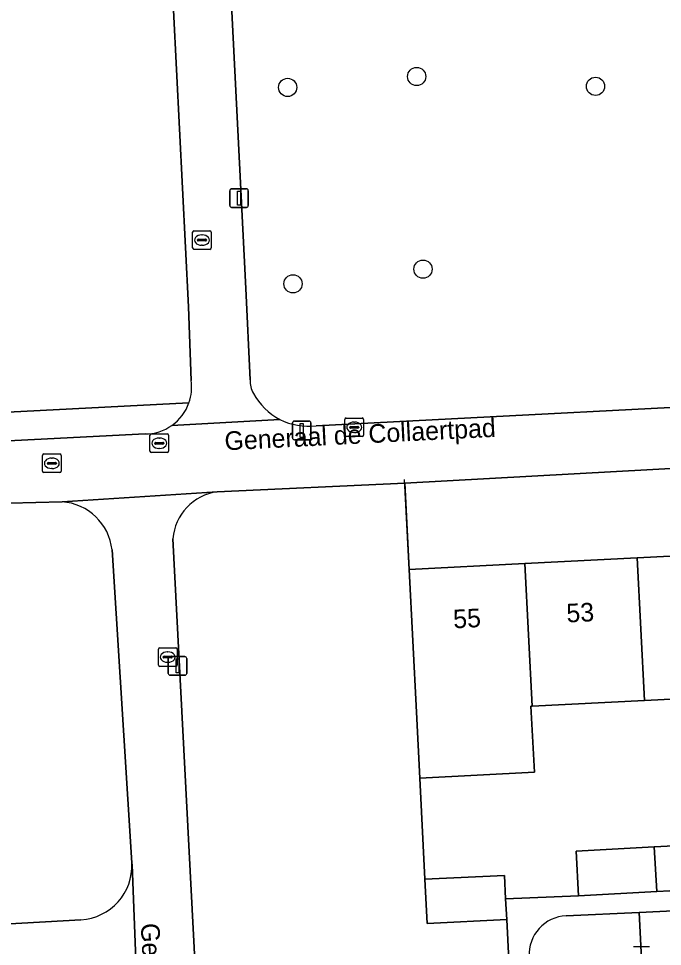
# Model space of a CAD drawing. Extents: x 161084 to 161928, y 385354 to 386522.
# Drawn here: x 161354.6 to 161389.16, y 385539.9 to 385589.73 of the extents above; entities that cross this region are included whole.
import ezdxf

# ---------------------------------------------------------------- set-up
doc = ezdxf.new("R2010")
doc.units = 0
for name, color, linetype in [('IMGEO_Boom', 7, 'Continuous'), ('IMGEO_Brandkraan', 7, 'Continuous'), ('IMGEO_Erf', 7, 'Continuous'), ('IMGEO_Groenvoorziening', 7, 'Continuous'), ('IMGEO_Hek', 7, 'Continuous'), ('IMGEO_Kolk', 7, 'Continuous'), ('IMGEO_Lichtmast', 7, 'Continuous'), ('IMGEO_Openbare_ruimte_label', 7, 'Continuous'), ('IMGEO_Pand', 7, 'Continuous'), ('IMGEO_Pand_nummerreeks', 7, 'Continuous'), ('IMGEO_Parkeervlak_open', 7, 'Continuous'), ('IMGEO_Rijbaan_lokaal_open', 7, 'Continuous'), ('IMGEO_Rioolput', 7, 'Continuous'), ('IMGEO_Voetpad_open', 7, 'Continuous')]:
    doc.layers.add(name, color=color, linetype=linetype)

msp = doc.modelspace()

# ---------------------------------------------------------------- linework, layer by layer
at = {"layer": 'IMGEO_Boom'}
for centre in [(161375.974, 385586.619), (161369.05, 385586.033), (161385.569, 385586.093), (161376.308, 385576.276), (161369.332, 385575.487)]:
    msp.add_circle(centre, 0.489, dxfattribs=at)
at = {"layer": 'IMGEO_Brandkraan'}
for p, q in [((161355.965, 385566.348), (161356.817, 385566.348)), ((161355.89, 385565.422), (161355.89, 385566.274)), ((161356.149, 385565.842), (161356.149, 385565.854)), ((161356.587, 385565.805), (161356.189, 385565.805)), ((161356.192, 385565.891), (161356.59, 385565.891)), ((161356.378, 385566.128), (161356.403, 385566.128)), ((161356.633, 385565.854), (161356.633, 385565.842)), ((161356.891, 385566.274), (161356.891, 385565.422)), ((161356.817, 385565.348), (161355.965, 385565.348)), ((161356.401, 385565.568), (161356.376, 385565.568))]:
    msp.add_line(p, q, dxfattribs=at)
for points in [[(161355.965, 385566.348), (161356.817, 385566.348)], [(161355.89, 385565.422), (161355.89, 385566.274)], [(161356.891, 385566.274), (161356.891, 385565.422)], [(161356.817, 385565.348), (161355.965, 385565.348)]]:
    msp.add_lwpolyline(points, dxfattribs=at)
for centre, radius, start, end in [((161355.967, 385566.272), 0.0765, 91.552, 178.448), ((161355.967, 385566.272), 0.0765, 91.552, 178.448), ((161356.815, 385566.272), 0.0765, 1.552, 88.448), ((161356.815, 385566.272), 0.0765, 1.552, 88.448), ((161356.189, 385565.851), 0.0403, 85.8775, 175.7526), ((161356.186, 385565.841), 0.0366, 178.938, 274.7102), ((161356.59, 385565.848), 0.043, 264.8664, 352.4533), ((161356.594, 385565.853), 0.0386, 1.7309, 96.639), ((161355.967, 385565.424), 0.0765, 181.552, 268.448), ((161355.967, 385565.424), 0.0765, 181.552, 268.448), ((161356.815, 385565.424), 0.0765, 271.552, 358.448), ((161356.815, 385565.424), 0.0765, 271.552, 358.448)]:
    msp.add_arc(centre, radius, start, end, dxfattribs=at)
for centre, major_axis, ratio, start_param, end_param in [((161356.377, 385565.848), (-0.387, 0.002), 0.722429, 4.712389, 7.853982), ((161356.402, 385565.848), (-0.39, 0.002), 0.717154, 1.570796, 4.712389)]:
    msp.add_ellipse(centre, major_axis=major_axis, ratio=ratio, start_param=start_param, end_param=end_param, dxfattribs=at)
at = {"layer": 'IMGEO_Erf'}
for points in [[(161363.866, 385570.302), (161363.733, 385574.245), (161361.948, 385609.312), (161361.09, 385626.303)], [(161305.114, 385623.524), (161305.617, 385619.727), (161306.439, 385613.522), (161312.203, 385570.057), (161312.559, 385567.353), (161314.112, 385566.538), (161363.75, 385569.097)], [(161394.225, 385553.42), (161388.198, 385553.11), (161382.171, 385552.8), (161382.104, 385552.797), (161382.286, 385549.253), (161376.143, 385548.938), (161376.412, 385543.507), (161380.684, 385543.72), (161380.746, 385542.467), (161384.664, 385542.622), (161384.534, 385545.022), (161388.726, 385545.248), (161392.919, 385545.474)]]:
    msp.add_lwpolyline(points, dxfattribs=at)
msp.add_lwpolyline([(161417.869, 385567.12), (161375.334, 385564.785), (161375.573, 385560.144), (161381.776, 385560.463), (161387.803, 385560.773), (161393.83, 385561.083), (161399.858, 385561.394), (161405.885, 385561.704), (161411.912, 385562.014), (161418.115, 385562.333)], close=True, dxfattribs=at)
msp.add_arc((161361.36, 385569.935), 2.533, 340.6761, 8.3266, dxfattribs=at)
at = {"layer": 'IMGEO_Groenvoorziening'}
for points in [[(161365.189, 385607.142), (161366.798, 385575.235), (161367.037, 385570.33)], [(161370.578, 385567.869), (161427.283, 385570.797)], [(161363.75, 385569.097), (161314.112, 385566.538), (161312.559, 385567.353)], [(161315.258, 385565.06), (161361.391, 385567.423)], [(161376.143, 385548.938), (161375.967, 385552.481), (161375.573, 385560.144), (161375.334, 385564.785), (161365.266, 385564.318)], [(161356.944, 385563.781), (161352.693, 385563.68), (161352.927, 385559.001), (161353.31, 385551.35), (161353.823, 385541.093), (161357.948, 385541.336)], [(161362.888, 385561.798), (161364.617, 385528.51)], [(161360.681, 385544.392), (161359.622, 385561.202)], [(161367.825, 385525.64), (161381.537, 385526.414), (161380.802, 385541.342), (161376.531, 385541.129), (161376.412, 385543.507), (161376.143, 385548.938)]]:
    msp.add_lwpolyline(points, dxfattribs=at)
for centre, radius, start, end in [((161368.129, 385570.214), 1.098, 173.96, 213.8527), ((161370.146, 385571.152), 3.313, 207.8627, 242.6688), ((161361.385, 385569.934), 2.509, 305.3066, 340.5004), ((161361.377, 385569.946), 2.523, 270.3183, 305.3092), ((161370.142, 385571.151), 3.311, 242.7336, 277.5719), ((161365.643, 385561.58), 2.763, 97.8371, 175.4842), ((161356.738, 385560.887), 2.901, 6.2283, 85.9294), ((161357.782, 385544.234), 2.903, 273.2765, 3.1105)]:
    msp.add_arc(centre, radius, start, end, dxfattribs=at)
at = {"layer": 'IMGEO_Hek'}
for points in [[(161375.573, 385560.144), (161375.324, 385564.98)], [(161375.967, 385552.481), (161376.412, 385543.507)]]:
    msp.add_lwpolyline(points, dxfattribs=at)
at = {"layer": 'IMGEO_Kolk'}
for p, q in [((161363.944, 385577.411), (161363.944, 385578.263)), ((161364.019, 385578.337), (161364.871, 385578.337)), ((161364.945, 385578.263), (161364.945, 385577.411)), ((161364.203, 385577.831), (161364.203, 385577.843)), ((161364.641, 385577.794), (161364.243, 385577.794)), ((161364.246, 385577.88), (161364.644, 385577.88)), ((161364.432, 385578.117), (161364.457, 385578.117)), ((161364.687, 385577.843), (161364.687, 385577.831)), ((161364.871, 385577.337), (161364.019, 385577.337)), ((161364.455, 385577.557), (161364.43, 385577.557)), ((161372.118, 385567.355), (161372.118, 385568.207)), ((161372.193, 385568.281), (161373.045, 385568.281)), ((161372.42, 385567.824), (161372.818, 385567.824)), ((161372.606, 385568.061), (161372.631, 385568.061)), ((161373.119, 385568.207), (161373.119, 385567.355)), ((161372.377, 385567.775), (161372.377, 385567.787)), ((161372.815, 385567.738), (161372.417, 385567.738)), ((161372.629, 385567.501), (161372.604, 385567.501)), ((161372.861, 385567.787), (161372.861, 385567.775)), ((161373.045, 385567.281), (161372.193, 385567.281)), ((161362.111, 385555.016), (161362.111, 385555.868)), ((161362.186, 385555.942), (161363.038, 385555.942)), ((161363.112, 385555.868), (161363.112, 385555.016)), ((161362.37, 385555.436), (161362.37, 385555.448)), ((161362.808, 385555.399), (161362.41, 385555.399)), ((161362.413, 385555.485), (161362.811, 385555.485)), ((161362.599, 385555.722), (161362.624, 385555.722)), ((161362.854, 385555.448), (161362.854, 385555.436)), ((161363.038, 385554.942), (161362.186, 385554.942)), ((161362.622, 385555.162), (161362.597, 385555.162)), ((161387.609, 385539.902), (161388.461, 385539.902))]:
    msp.add_line(p, q, dxfattribs=at)
for points in [[(161363.944, 385577.411), (161363.944, 385578.263)], [(161364.019, 385578.337), (161364.871, 385578.337)], [(161364.945, 385578.263), (161364.945, 385577.411)], [(161364.871, 385577.337), (161364.019, 385577.337)], [(161372.118, 385567.355), (161372.118, 385568.207)], [(161372.193, 385568.281), (161373.045, 385568.281)], [(161373.119, 385568.207), (161373.119, 385567.355)], [(161373.045, 385567.281), (161372.193, 385567.281)], [(161362.111, 385555.016), (161362.111, 385555.868)], [(161362.186, 385555.942), (161363.038, 385555.942)], [(161363.112, 385555.868), (161363.112, 385555.016)], [(161363.038, 385554.942), (161362.186, 385554.942)], [(161387.609, 385539.902), (161388.461, 385539.902)]]:
    msp.add_lwpolyline(points, dxfattribs=at)
for centre, radius, start, end in [((161364.021, 385578.261), 0.0765, 91.552, 178.448), ((161364.021, 385578.261), 0.0765, 91.552, 178.448), ((161364.869, 385578.261), 0.0765, 1.552, 88.448), ((161364.869, 385578.261), 0.0765, 1.552, 88.448), ((161364.243, 385577.84), 0.0403, 85.8775, 175.7526), ((161364.24, 385577.83), 0.0366, 178.938, 274.7102), ((161364.644, 385577.837), 0.043, 264.8664, 352.4533), ((161364.648, 385577.842), 0.0386, 1.7309, 96.639), ((161364.021, 385577.413), 0.0765, 181.552, 268.448), ((161364.021, 385577.413), 0.0765, 181.552, 268.448), ((161364.869, 385577.413), 0.0765, 271.552, 358.448), ((161364.869, 385577.413), 0.0765, 271.552, 358.448), ((161372.195, 385568.205), 0.0765, 91.552, 178.448), ((161372.195, 385568.205), 0.0765, 91.552, 178.448), ((161372.417, 385567.784), 0.0403, 85.8775, 175.7526), ((161372.822, 385567.786), 0.0386, 1.7309, 96.639), ((161373.043, 385568.205), 0.0765, 1.552, 88.448), ((161373.043, 385568.205), 0.0765, 1.552, 88.448), ((161372.195, 385567.357), 0.0765, 181.552, 268.448), ((161372.195, 385567.357), 0.0765, 181.552, 268.448), ((161372.414, 385567.774), 0.0366, 178.938, 274.7102), ((161372.818, 385567.781), 0.043, 264.8664, 352.4533), ((161373.043, 385567.357), 0.0765, 271.552, 358.448), ((161373.043, 385567.357), 0.0765, 271.552, 358.448), ((161362.188, 385555.866), 0.0765, 91.552, 178.448), ((161362.188, 385555.866), 0.0765, 91.552, 178.448), ((161363.036, 385555.866), 0.0765, 1.552, 88.448), ((161363.036, 385555.866), 0.0765, 1.552, 88.448), ((161362.41, 385555.445), 0.0403, 85.8775, 175.7526), ((161362.407, 385555.435), 0.0366, 178.938, 274.7102), ((161362.811, 385555.442), 0.043, 264.8664, 352.4533), ((161362.815, 385555.447), 0.0386, 1.7309, 96.639), ((161362.188, 385555.018), 0.0765, 181.552, 268.448), ((161362.188, 385555.018), 0.0765, 181.552, 268.448), ((161363.036, 385555.018), 0.0765, 271.552, 358.448), ((161363.036, 385555.018), 0.0765, 271.552, 358.448)]:
    msp.add_arc(centre, radius, start, end, dxfattribs=at)
for centre, major_axis, ratio, start_param, end_param in [((161364.431, 385577.837), (-0.387, 0.002), 0.722429, 4.712389, 7.853982), ((161364.456, 385577.837), (-0.39, 0.002), 0.717154, 1.570796, 4.712389), ((161372.605, 385567.781), (-0.387, 0.002), 0.722429, 4.712389, 7.853982), ((161372.63, 385567.781), (-0.39, 0.002), 0.717154, 1.570796, 4.712389), ((161362.598, 385555.442), (-0.387, 0.002), 0.722429, 4.712389, 7.853982), ((161362.623, 385555.442), (-0.39, 0.002), 0.717154, 1.570796, 4.712389)]:
    msp.add_ellipse(centre, major_axis=major_axis, ratio=ratio, start_param=start_param, end_param=end_param, dxfattribs=at)
at = {"layer": 'IMGEO_Lichtmast'}
for p, q in [((161365.941, 385579.688), (161365.941, 385580.488)), ((161365.941, 385580.488), (161365.941, 385579.688)), ((161366.041, 385580.588), (161366.831, 385580.588)), ((161366.831, 385580.588), (161366.041, 385580.588)), ((161366.931, 385580.488), (161366.931, 385579.688)), ((161366.931, 385579.688), (161366.931, 385580.488)), ((161366.831, 385579.588), (161366.041, 385579.588)), ((161366.041, 385579.588), (161366.831, 385579.588)), ((161369.306, 385567.213), (161369.306, 385568.013)), ((161369.306, 385568.013), (161369.306, 385567.213)), ((161369.406, 385568.113), (161370.196, 385568.113)), ((161370.196, 385568.113), (161369.406, 385568.113)), ((161370.296, 385568.013), (161370.296, 385567.213)), ((161370.296, 385567.213), (161370.296, 385568.013)), ((161370.196, 385567.113), (161369.406, 385567.113)), ((161369.406, 385567.113), (161370.196, 385567.113)), ((161362.638, 385554.569), (161362.638, 385555.369)), ((161362.638, 385555.369), (161362.638, 385554.569)), ((161362.738, 385555.469), (161363.528, 385555.469)), ((161363.528, 385555.469), (161362.738, 385555.469)), ((161363.628, 385555.369), (161363.628, 385554.569)), ((161363.628, 385554.569), (161363.628, 385555.369)), ((161363.528, 385554.469), (161362.738, 385554.469)), ((161362.738, 385554.469), (161363.528, 385554.469))]:
    msp.add_line(p, q, dxfattribs=at)
for points in [[(161366.361, 385580.463), (161366.511, 385580.463), (161366.511, 385579.713), (161366.361, 385579.713), (161366.361, 385580.463)], [(161369.726, 385567.988), (161369.876, 385567.988), (161369.876, 385567.238), (161369.726, 385567.238), (161369.726, 385567.988)], [(161363.058, 385555.344), (161363.208, 385555.344), (161363.208, 385554.594), (161363.058, 385554.594), (161363.058, 385555.344)]]:
    msp.add_lwpolyline(points, dxfattribs=at)
for centre, start, end in [((161366.041, 385580.488), 90, 180), ((161366.041, 385580.488), 90, 180), ((161366.831, 385580.488), 0, 90), ((161366.831, 385580.488), 360, 90), ((161366.041, 385579.688), 180, 270), ((161366.041, 385579.688), 180, 270), ((161366.831, 385579.688), 270, 0), ((161366.831, 385579.688), 270, 0), ((161369.406, 385568.013), 90, 180), ((161369.406, 385568.013), 90, 180), ((161370.196, 385568.013), 0, 90), ((161370.196, 385568.013), 360, 90), ((161369.406, 385567.213), 180, 270), ((161369.406, 385567.213), 180, 270), ((161370.196, 385567.213), 270, 0), ((161370.196, 385567.213), 270, 0), ((161362.738, 385555.369), 90, 180), ((161362.738, 385555.369), 90, 180), ((161363.528, 385555.369), 0, 90), ((161363.528, 385555.369), 360, 90), ((161362.738, 385554.569), 180, 270), ((161362.738, 385554.569), 180, 270), ((161363.528, 385554.569), 270, 0), ((161363.528, 385554.569), 270, 0)]:
    msp.add_arc(centre, 0.1, start, end, dxfattribs=at)
at = {"layer": 'IMGEO_Pand'}
for points in [[(161393.83, 385561.083), (161387.803, 385560.773), (161388.198, 385553.11), (161394.225, 385553.42)], [(161381.776, 385560.463), (161375.573, 385560.144), (161375.967, 385552.481), (161376.143, 385548.938), (161382.286, 385549.253), (161382.104, 385552.797), (161382.171, 385552.8)], [(161387.803, 385560.773), (161381.776, 385560.463), (161382.171, 385552.8), (161388.198, 385553.11)], [(161393.049, 385543.074), (161392.919, 385545.474), (161388.726, 385545.248), (161388.856, 385542.848)], [(161388.856, 385542.848), (161388.726, 385545.248), (161384.534, 385545.022), (161384.664, 385542.622)], [(161380.746, 385542.467), (161380.684, 385543.72), (161376.412, 385543.507), (161376.531, 385541.129), (161380.802, 385541.342)]]:
    msp.add_lwpolyline(points, close=True, dxfattribs=at)
at = {"layer": 'IMGEO_Parkeervlak_open'}
msp.add_lwpolyline([(161384.439, 385526.54), (161388.666, 385526.781), (161387.919, 385541.732), (161383.986, 385541.548)], dxfattribs=at)
msp.add_arc((161384.083, 385539.472), 2.078, 92.6641, 182.922, dxfattribs=at)
at = {"layer": 'IMGEO_Rijbaan_lokaal_open'}
for points in [[(161396.75, 385542.155), (161387.919, 385541.732)], [(161387.919, 385541.732), (161388.666, 385526.781)]]:
    msp.add_lwpolyline(points, dxfattribs=at)
at = {"layer": 'IMGEO_Rioolput'}
for p, q in [((161361.655, 385566.5), (161361.655, 385567.352)), ((161361.73, 385567.426), (161362.582, 385567.426)), ((161362.656, 385567.352), (161362.656, 385566.5)), ((161361.914, 385566.92), (161361.914, 385566.932)), ((161362.352, 385566.883), (161361.954, 385566.883)), ((161361.957, 385566.969), (161362.355, 385566.969)), ((161362.143, 385567.206), (161362.168, 385567.206)), ((161362.398, 385566.932), (161362.398, 385566.92)), ((161362.582, 385566.426), (161361.73, 385566.426)), ((161362.166, 385566.646), (161362.141, 385566.646))]:
    msp.add_line(p, q, dxfattribs=at)
for points in [[(161361.655, 385566.5), (161361.655, 385567.352)], [(161361.73, 385567.426), (161362.582, 385567.426)], [(161362.656, 385567.352), (161362.656, 385566.5)], [(161362.582, 385566.426), (161361.73, 385566.426)]]:
    msp.add_lwpolyline(points, dxfattribs=at)
for centre, radius, start, end in [((161361.732, 385567.35), 0.0765, 91.552, 178.448), ((161361.732, 385567.35), 0.0765, 91.552, 178.448), ((161362.58, 385567.35), 0.0765, 1.552, 88.448), ((161362.58, 385567.35), 0.0765, 1.552, 88.448), ((161361.954, 385566.929), 0.0403, 85.8775, 175.7526), ((161361.951, 385566.919), 0.0366, 178.938, 274.7102), ((161362.355, 385566.926), 0.043, 264.8664, 352.4533), ((161362.359, 385566.931), 0.0386, 1.7309, 96.639), ((161361.732, 385566.502), 0.0765, 181.552, 268.448), ((161361.732, 385566.502), 0.0765, 181.552, 268.448), ((161362.58, 385566.502), 0.0765, 271.552, 358.448), ((161362.58, 385566.502), 0.0765, 271.552, 358.448)]:
    msp.add_arc(centre, radius, start, end, dxfattribs=at)
for centre, major_axis, ratio, start_param, end_param in [((161362.142, 385566.926), (-0.387, 0.002), 0.722429, 4.712389, 7.853982), ((161362.167, 385566.926), (-0.39, 0.002), 0.717154, 1.570796, 4.712389)]:
    msp.add_ellipse(centre, major_axis=major_axis, ratio=ratio, start_param=start_param, end_param=end_param, dxfattribs=at)
at = {"layer": 'IMGEO_Voetpad_open'}
for points in [[(161365.189, 385607.142), (161364.763, 385614.768), (161364.165, 385626.458), (161361.09, 385626.303), (161361.948, 385609.312), (161363.733, 385574.245), (161363.866, 385570.302)], [(161367.037, 385570.33), (161366.798, 385575.235), (161365.189, 385607.142)], [(161427.283, 385570.797), (161370.578, 385567.869)], [(161315.891, 385561.977), (161322.232, 385562.287), (161352.693, 385563.68), (161356.944, 385563.781), (161365.266, 385564.318), (161375.334, 385564.785), (161417.869, 385567.12), (161423.5, 385567.403), (161431.179, 385567.888), (161433.457, 385568.003), (161441.569, 385568.411), (161484.187, 385570.555)], [(161362.835, 385567.887), (161368.625, 385568.208)], [(161368.625, 385568.208), (161362.835, 385567.887)], [(161361.391, 385567.423), (161315.258, 385565.06)], [(161365.266, 385564.318), (161356.944, 385563.781)], [(161364.961, 385520.497), (161364.955, 385520.547), (161364.615, 385528.479), (161364.617, 385528.51), (161362.888, 385561.798)], [(161359.622, 385561.202), (161360.681, 385544.392), (161360.7, 385544.287), (161361.004, 385536.419), (161362.922, 385500), (161363.746, 385484.359), (161363.753, 385484.323), (161364.139, 385477.899), (161364.135, 385477.846), (161365.148, 385456.333)], [(161361.004, 385536.419), (161360.7, 385544.287), (161360.681, 385544.392)], [(161383.986, 385541.548), (161387.919, 385541.732), (161396.75, 385542.155), (161396.693, 385543.204), (161393.049, 385543.074), (161388.856, 385542.848), (161384.664, 385542.622), (161380.746, 385542.467), (161380.802, 385541.342), (161381.537, 385526.414), (161367.825, 385525.64)], [(161357.948, 385541.336), (161353.823, 385541.093), (161351.924, 385540.981), (161347.624, 385540.8), (161343.554, 385540.629), (161339.928, 385540.438), (161338.638, 385540.364), (161335.583, 385540.19), (161331.499, 385539.957), (161328.077, 385539.76)]]:
    msp.add_lwpolyline(points, dxfattribs=at)
for centre, radius, start, end in [((161361.36, 385569.935), 2.533, 340.6761, 8.3266), ((161368.129, 385570.214), 1.098, 173.96, 213.8527), ((161370.146, 385571.152), 3.313, 207.8627, 242.6688), ((161361.385, 385569.934), 2.509, 305.3066, 340.5004), ((161361.377, 385569.946), 2.523, 270.3183, 305.3092), ((161370.142, 385571.151), 3.311, 242.7336, 277.5719), ((161365.643, 385561.58), 2.763, 97.8371, 175.4842), ((161356.738, 385560.887), 2.901, 6.2283, 85.9294), ((161357.782, 385544.234), 2.903, 273.2765, 3.1105), ((161384.083, 385539.472), 2.078, 92.6641, 182.922)]:
    msp.add_arc(centre, radius, start, end, dxfattribs=at)

# ---------------------------------------------------------------- texts
at = {"layer": 'IMGEO_Openbare_ruimte_label'}
for s, rotation, p in [('Generaal de Collaertpad', 2.8653, (161365.683, 385566.544)), ('Generaal de Rhoopad', 272.9225, (161361.163, 385541.131))]:
    msp.add_text(s, height=1, rotation=rotation, dxfattribs=at).set_placement(p)
at = {"layer": 'IMGEO_Pand_nummerreeks'}
for s, rotation, p in [('53', 2.9456, (161384.032, 385557.295)), ('55', 2.945, (161377.955, 385556.982))]:
    msp.add_text(s, height=1, rotation=rotation, dxfattribs=at).set_placement(p)

doc.saveas('drawing.dxf')
